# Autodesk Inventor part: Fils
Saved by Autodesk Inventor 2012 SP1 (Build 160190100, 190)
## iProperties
Created: 2014-12
Part Number: Fils
Material: Default
Document SubType Name: Modeling
Designer: Bruno
Density: 1 g/cm^3
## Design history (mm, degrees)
node "Fils1"
node "Fils"
node "Fils_1"
node "Fils_2"
node "Base1"
node "Base2"
node "Base3"
